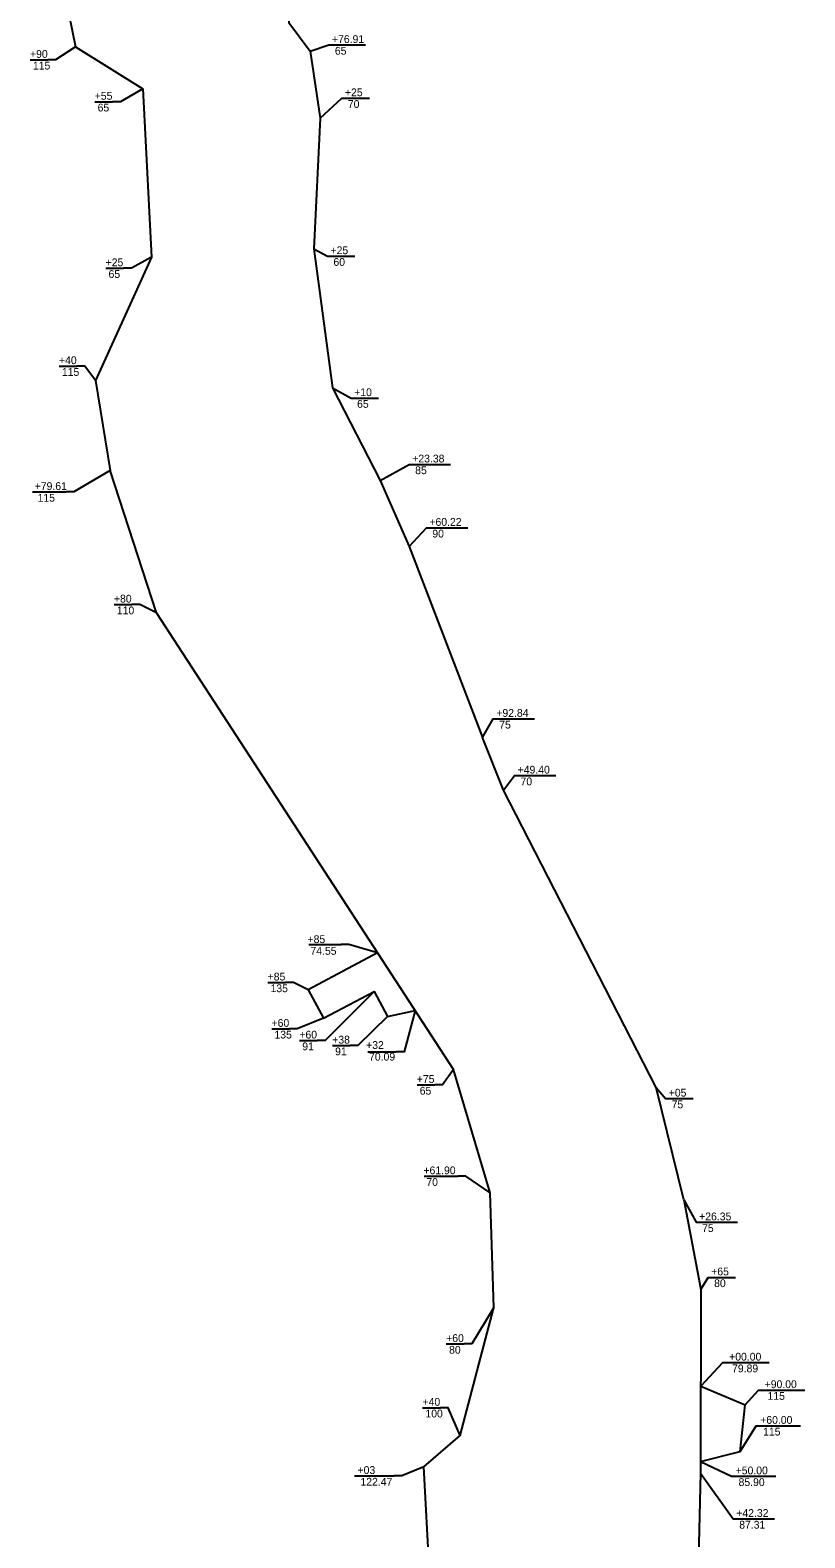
# Model space of a CAD drawing. Extents: x 979729 to 993523, y 1834148 to 1845433.
# Drawn here: x 992349 to 992945, y 1840790 to 1841951 of the extents above; entities that cross this region are included whole.
import ezdxf

# ---------------------------------------------------------------- set-up
doc = ezdxf.new("R2010")
doc.units = 0
for name, color, linetype in [('51', 7, 'Continuous'), ('53', 7, 'Continuous'), ('R_Draft', 7, 'Continuous')]:
    doc.layers.add(name, color=color, linetype=linetype)

msp = doc.modelspace()

# ---------------------------------------------------------------- linework, layer by layer
at = {"layer": '51'}
for p, q in [((992357.5, 1842065), (992383.4, 1841938.6)), ((992383.4, 1841938.6), (992435.2, 1841906.3)), ((992563.9, 1841935.1), (992571.6, 1841883.5)), ((992435.2, 1841906.3), (992442, 1841776.5)), ((992571.6, 1841883.5), (992566.9, 1841783.1)), ((992566.9, 1841783.1), (992581.3, 1841675.9)), ((992442, 1841776.5), (992398.8, 1841681.5)), ((992398.8, 1841681.5), (992410, 1841612.4)), ((992581.3, 1841675.9), (992617.8, 1841604.6)), ((992712.8, 1841366.1), (992696.7, 1841406.8)), ((992830.2, 1841137.3), (992712.8, 1841366.1)), ((992712.8, 1841366.1), (992712.8, 1841366.1)), ((992851.7, 1841050.6), (992830.2, 1841137.3)), ((992851.7, 1841050.6), (992864.7, 1840981.6)), ((992864.7, 1840981.6), (992864.5, 1840840.2)), ((992657.9, 1840724.2), (992651.4, 1840845)), ((992864.5, 1840840.2), (992862.7, 1840762.3))]:
    msp.add_line(p, q, dxfattribs=at)
for points in [[(992553.3, 1842135.6), (992542.9, 1842047.2), (992547.7, 1841957.3), (992563.9, 1841935.1)], [(992702.6, 1841056.2), (992674.3, 1841151.1), (992445.8, 1841502.8), (992410, 1841612.4)], [(992617.8, 1841604.6), (992640.3, 1841553.7)], [(992640.3, 1841553.7), (992696.7, 1841406.8)], [(992651.4, 1840845), (992679.4, 1840869.3), (992705.3, 1840967.9), (992702.6, 1841056.2)]]:
    msp.add_lwpolyline(points, dxfattribs=at)
at = {"layer": '53'}
for p, q in [((992864.6, 1840907.1), (992898.8, 1840892.9)), ((992895, 1840856.8), (992898.8, 1840892.9)), ((992864.5, 1840849.2), (992895, 1840856.8))]:
    msp.add_line(p, q, dxfattribs=at)
msp.add_lwpolyline([(992615.9, 1841241), (992562.6, 1841212.5), (992574.4, 1841190.5), (992613.2, 1841211.2), (992623.6, 1841191.9), (992644.8, 1841196.4)], dxfattribs=at)
at = {"layer": 'R_Draft'}
for p, q in [((992584.5, 1841940), (992606.7, 1841940)), ((992348.5, 1841928.6), (992362.1, 1841928.6)), ((992398.4, 1841896.3), (992412, 1841896.3)), ((992594.5, 1841899), (992609.6, 1841899)), ((992583.3, 1841777.4), (992598.4, 1841777.4)), ((992406.8, 1841768.1), (992420.4, 1841768.1)), ((992370.8, 1841692.7), (992384.5, 1841692.7)), ((992601.5, 1841668.1), (992616.6, 1841668.1)), ((992646.3, 1841617), (992672.1, 1841617)), ((992350.2, 1841595.8), (992376.2, 1841595.8)), ((992659.5, 1841568.2), (992685.3, 1841568.2)), ((992413.2, 1841509.1), (992426.8, 1841509.1)), ((992710.9, 1841421.1), (992736.8, 1841421.1)), ((992727.3, 1841377.4), (992753.1, 1841377.4)), ((992563, 1841247.3), (992587.8, 1841247.3)), ((992531.4, 1841218.1), (992545.1, 1841218.1)), ((992534.4, 1841182.4), (992548.1, 1841182.4)), ((992555.9, 1841173.4), (992569.5, 1841173.4)), ((992581.2, 1841169.5), (992594.8, 1841169.5)), ((992608.3, 1841164.6), (992630.3, 1841164.6)), ((992646.3, 1841139.2), (992659.9, 1841139.2)), ((992843.6, 1841128.7), (992858.7, 1841128.7)), ((992651.8, 1841068.9), (992677.9, 1841068.9)), ((992867, 1841033.4), (992892.8, 1841033.4)), ((992876.4, 1840991), (992891.5, 1840991)), ((992668.8, 1840939.7), (992682.5, 1840939.7)), ((992887.5, 1840925.4), (992917.4, 1840925.4)), ((992915.1, 1840904.2), (992944.7, 1840904.2)), ((992650.6, 1840890.6), (992664.3, 1840890.6)), ((992913.2, 1840876.7), (992941.3, 1840876.7)), ((992598.1, 1840838.1), (992628.6, 1840838.1)), ((992894.3, 1840837.8), (992922.4, 1840837.8)), ((992895.6, 1840805), (992921.4, 1840805))]:
    msp.add_line(p, q, dxfattribs=at)
for points in [[(992383.4, 1841938.6), (992368.1, 1841928.6), (992362.1, 1841928.6)], [(992563.9, 1841935.1), (992578.5, 1841940), (992584.5, 1841940)], [(992435.2, 1841906.3), (992418, 1841896.3), (992412, 1841896.3)], [(992571.6, 1841883.5), (992588.5, 1841899), (992594.5, 1841899)], [(992566.9, 1841783.1), (992577.3, 1841777.4), (992583.3, 1841777.4)], [(992442, 1841776.5), (992426.4, 1841768.1), (992420.4, 1841768.1)], [(992398.8, 1841681.5), (992390.5, 1841692.7), (992384.5, 1841692.7)], [(992581.3, 1841675.9), (992595.5, 1841668.1), (992601.5, 1841668.1)], [(992410, 1841612.4), (992382.2, 1841595.8), (992376.2, 1841595.8)], [(992617.8, 1841604.6), (992640.3, 1841617), (992646.3, 1841617)], [(992640.3, 1841553.7), (992653.5, 1841568.2), (992659.5, 1841568.2)], [(992445.8, 1841502.8), (992432.8, 1841509.1), (992426.8, 1841509.1)], [(992696.7, 1841406.8), (992704.9, 1841421.1), (992710.9, 1841421.1)], [(992712.8, 1841366.1), (992721.3, 1841377.4), (992727.3, 1841377.4)], [(992615.9, 1841241), (992593.8, 1841247.3), (992587.8, 1841247.3)], [(992562.6, 1841212.5), (992551.1, 1841218.1), (992545.1, 1841218.1)], [(992613.2, 1841211.2), (992575.5, 1841173.4), (992569.5, 1841173.4)], [(992574.4, 1841190.5), (992554.1, 1841182.4), (992548.1, 1841182.4)], [(992623.6, 1841191.9), (992600.8, 1841169.5), (992594.8, 1841169.5)], [(992644.8, 1841196.4), (992636.3, 1841164.6), (992630.3, 1841164.6)], [(992674.3, 1841151.1), (992665.9, 1841139.2), (992659.9, 1841139.2)], [(992830.2, 1841137.3), (992837.6, 1841128.7), (992843.6, 1841128.7)], [(992702.6, 1841056.2), (992683.9, 1841068.9), (992677.9, 1841068.9)], [(992851.7, 1841050.6), (992861, 1841033.4), (992867, 1841033.4)], [(992864.7, 1840981.6), (992870.4, 1840991), (992876.4, 1840991)], [(992705.3, 1840967.9), (992688.5, 1840939.7), (992682.5, 1840939.7)], [(992864.6, 1840907.1), (992881.5, 1840925.4), (992887.5, 1840925.4)], [(992898.8, 1840892.9), (992909.1, 1840904.2), (992915.1, 1840904.2)], [(992679.4, 1840869.3), (992670.3, 1840890.6), (992664.3, 1840890.6)], [(992895, 1840856.8), (992907.2, 1840876.7), (992913.2, 1840876.7)], [(992651.4, 1840845), (992634.6, 1840838.1), (992628.6, 1840838.1)], [(992864.5, 1840849.2), (992888.3, 1840837.8), (992894.3, 1840837.8)], [(992864.5, 1840840.2), (992889.6, 1840805), (992895.6, 1840805)]]:
    msp.add_lwpolyline(points, dxfattribs=at)

# ---------------------------------------------------------------- texts
for s, p in [('+76.91', (992580.8, 1841941.5)), ('+90', (992348.4, 1841930.1)), (' 65', (992580.8, 1841932.5)), (' 115', (992348.4, 1841921.1)), ('+55', (992398.2, 1841897.8)), ('+25', (992590.8, 1841900.5)), (' 70', (992590.8, 1841891.5)), (' 65', (992398.2, 1841888.8)), ('+25', (992579.7, 1841778.9)), ('+25', (992406.6, 1841769.6)), (' 60', (992579.7, 1841769.9)), (' 65', (992406.6, 1841760.6)), ('+40', (992370.7, 1841694.2)), (' 115', (992370.7, 1841685.2)), ('+10', (992597.9, 1841669.6)), (' 65', (992597.9, 1841660.6)), ('+23.38', (992642.6, 1841618.5)), (' 85', (992642.6, 1841609.5)), ('+79.61', (992352, 1841597.3)), (' 115', (992352, 1841588.3)), ('+60.22', (992655.8, 1841569.7)), (' 90', (992655.8, 1841560.7)), ('+80', (992413, 1841510.6)), (' 110', (992413, 1841501.6)), ('+92.84', (992707.3, 1841422.6)), (' 75', (992707.3, 1841413.6)), ('+49.40', (992723.7, 1841378.9)), (' 70', (992723.7, 1841369.9)), ('+85', (992562, 1841248.4)), (' 74.55', (992562, 1841239.4)), ('+85', (992531.3, 1841219.6)), (' 135', (992531.3, 1841210.6)), ('+60', (992534.3, 1841183.9)), (' 135', (992534.3, 1841174.9)), ('+60', (992555.7, 1841174.9)), ('+38', (992581, 1841171)), (' 91', (992555.7, 1841165.9)), (' 91', (992581, 1841162)), ('+32', (992607.1, 1841166.9)), (' 70.09', (992607.1, 1841157.9)), ('+75', (992646.1, 1841140.7)), (' 65', (992646.1, 1841131.7)), ('+05', (992840, 1841130.2)), (' 75', (992840, 1841121.2)), ('+61.90', (992651.2, 1841070.4)), (' 70', (992651.2, 1841061.4)), ('+26.35', (992863.4, 1841034.9)), (' 75', (992863.4, 1841025.9)), ('+65', (992872.7, 1840992.5)), (' 80', (992872.7, 1840983.5)), ('+60', (992668.7, 1840941.2)), (' 80', (992668.7, 1840932.2)), ('+00.00', (992886.5, 1840926.9)), (' 79.89', (992886.5, 1840917.9)), ('+90.00', (992913.8, 1840905.7)), ('+40', (992650.5, 1840892.1)), (' 115', (992913.8, 1840896.7)), (' 100', (992650.5, 1840883.1)), ('+60.00', (992910.4, 1840878.2)), (' 115', (992910.4, 1840869.2)), ('+03', (992600.5, 1840839.6)), ('+50.00', (992891.5, 1840839.3)), (' 122.47', (992600.5, 1840830.6)), (' 85.90', (992891.5, 1840830.3)), ('+42.32', (992892, 1840806.5)), (' 87.31', (992892, 1840797.5))]:
    msp.add_text(s, height=6, rotation=360, dxfattribs=at).set_placement(p)

doc.saveas('drawing.dxf')
